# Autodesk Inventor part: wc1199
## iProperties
Shininess: 64.0
Length Units: 11272
Angle Units: 11279
Time Units: 11290
Mass Units: 11286
Length Display Precision: 3
Angle Display Precision: 2
Compacted: True
Part Number: wc1199
Document SubType Name: Modeling
Created: 2004-08
Designer: John Blackburn
Manufacturer: Standard
Standards Organization: Custom
Material: Phenolic
Density: 0.0
Volumn: 0.0
Area: 0.0
PropertySet Name: Model Information
Control State: 0
Master: False
Checked Out: False
Author: John Blackburn
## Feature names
1. Base1
